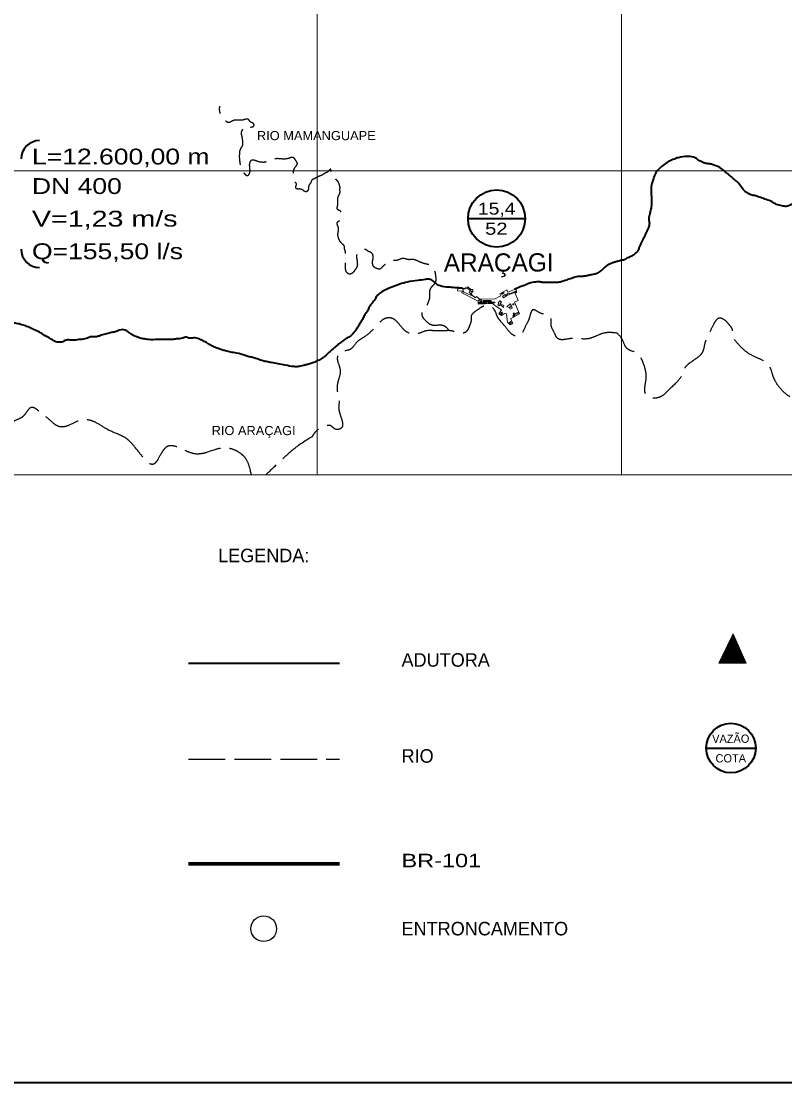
# Model space of a CAD drawing. Extents: x -4 to 42046, y -3 to 29697.
# Drawn here: x 27137 to 31133, y 10020 to 15575 of the extents above; entities that cross this region are included whole.
import ezdxf
from ezdxf.enums import TextEntityAlignment as Align

# ---------------------------------------------------------------- set-up
doc = ezdxf.new("R2010")
doc.units = 0
doc.header["$LTSCALE"] = 32
doc.linetypes.add('DOT_DASHED', pattern=[7.7, 5, -1.2, 0.3, -1.2])
doc.linetypes.add('LONG_DASHED', pattern=[7.5, 6, -1.5])
for name, color, linetype, lineweight in [('1', 7, 'DOT_DASHED', 13), ('4', 7, 'Continuous', 13), ('5', 7, 'LONG_DASHED', 25), ('6', 7, 'Continuous', 40), ('63', 7, 'Continuous', 25), ('8', 7, 'Continuous', 35), ('9', 7, 'Continuous', 40)]:
    doc.layers.add(name, color=color, linetype=linetype, lineweight=lineweight)

msp = doc.modelspace()

# ---------------------------------------------------------------- linework, layer by layer
at = {"layer": '1', "linetype": 'Continuous'}
for points in [[(29744.7, 14044.01), (29718.97, 14105.65), (29738.55, 14113.81), (29722.65, 14151.9), (29729.65, 14154.81), (29727.44, 14174.14), (29683.62, 14157.13), (29679.13, 14168.68), (29642.18, 14148.33), (29647.48, 14138.73), (29613.62, 14120.08), (29534.25, 14121.97), (29520.23, 14134.95), (29512.82, 14126.96), (29489.31, 14148.71), (29500.27, 14160.52), (29500.36, 14171.05), (29489.82, 14171.14), (29474.28, 14185.44), (29450.2, 14174.76), (29421.75, 14177.09), (29420.68, 14164.08), (29444.2, 14162.16), (29443.51, 14153.65), (29528.5, 14110.87), (29529.03, 14094.96), (29602.73, 14097.4), (29621.15, 14084.62), (29650.49, 14064.27), (29636.62, 14044.31), (29650.86, 14034.44), (29667.07, 14046.19), (29676.24, 14043.8), (29681.19, 13999.94), (29696.18, 13986.49), (29710.62, 13994.24), (29698.28, 14017.17)], [(29449.12, 14162.14), (29449.09, 14171.03), (29472.52, 14178.25), (29484.15, 14167.18), (29496.75, 14161.3), (29495.66, 14158.96), (29484.45, 14164.2), (29480.87, 14156.55), (29498.55, 14137.36), (29454.32, 14156.73)], [(29547.5, 14109.37), (29538.37, 14109.34), (29530.96, 14113.27), (29533.04, 14117.19), (29545.26, 14116.77)], [(29595.86, 14113.71), (29555.39, 14113.59), (29555.4, 14108.9), (29595.88, 14109.02)], [(29644.11, 14093.53), (29638.87, 14086.59), (29631.92, 14091.82), (29637.16, 14098.76), (29633.39, 14101.6), (29641.69, 14112.61), (29650.36, 14106.09), (29643.83, 14097.44), (29663, 14087.14), (29661.12, 14076.86)], [(29652.77, 14144.36), (29664.37, 14151.37), (29661.93, 14155.41), (29650.32, 14148.4)], [(29724.47, 14156.86), (29681.67, 14141.12), (29661.13, 14127.12), (29655.67, 14135.1), (29669.35, 14144.42), (29672.65, 14139.61), (29681.44, 14145.6), (29679.15, 14148.96), (29688.95, 14151.44), (29694.93, 14149.13), (29723.12, 14162.17)], [(29533.71, 14099.46), (29574.19, 14099.58), (29574.17, 14105.5), (29533.69, 14105.38)], [(29580.85, 14100.83), (29616.14, 14100.94), (29616.13, 14105.38), (29580.83, 14105.27)], [(29696.43, 14095.84), (29678.07, 14080.97), (29691.94, 14077.67), (29702.43, 14086.54)], [(29706.05, 14073.89), (29696.51, 14068.6), (29692.84, 14075.2), (29705.31, 14082.11)], [(29709.34, 14090.62), (29709.33, 14095.96), (29714.67, 14095.98), (29714.69, 14090.64)], [(29647.14, 14038.83), (29656.43, 14048.18), (29651.87, 14052.7), (29642.58, 14043.35)], [(29695.54, 13993.58), (29691.7, 13997.87), (29697.87, 14003.38), (29701.71, 13999.09)], [(29720.49, 14036.42), (29713.11, 14030.19), (29710.38, 14033.41), (29717.77, 14039.64)], [(29714.75, 14041.18), (29712.34, 14045.95), (29717.12, 14048.35), (29719.52, 14043.58)], [(29739.57, 14047.71), (29725.02, 14040.73), (29723.07, 14044.79), (29737.63, 14051.76)]]:
    msp.add_lwpolyline(points, close=True, dxfattribs=at)
at = {"layer": '4'}
for p, q in [((30814.89, 12269.39), (30878.99, 12333.49)), ((30817.49, 12274.82), (30878.12, 12335.45)), ((30820.09, 12280.25), (30877.25, 12337.41)), ((30822.69, 12285.68), (30876.38, 12339.36)), ((30825.29, 12291.11), (30875.51, 12341.32)), ((30827.89, 12296.54), (30874.64, 12343.28)), ((30830.5, 12301.97), (30873.77, 12345.24)), ((30833.1, 12307.4), (30872.9, 12347.2)), ((30835.7, 12312.83), (30872.03, 12349.16)), ((30838.3, 12318.25), (30871.17, 12351.12)), ((30840.9, 12323.68), (30870.3, 12353.08)), ((30843.5, 12329.11), (30869.43, 12355.04)), ((30846.1, 12334.54), (30868.56, 12357)), ((30848.7, 12339.97), (30867.69, 12358.96)), ((30851.3, 12345.4), (30866.82, 12360.92)), ((30853.91, 12350.83), (30865.95, 12362.88)), ((30856.51, 12356.26), (30865.08, 12364.84)), ((30859.11, 12361.69), (30864.21, 12366.8)), ((30861.71, 12367.12), (30863.34, 12368.76)), ((30788.88, 12215.09), (30887.68, 12313.89)), ((30791.48, 12220.52), (30886.81, 12315.85)), ((30791.57, 12214.96), (30888.54, 12311.93)), ((30794.08, 12225.95), (30885.94, 12317.81)), ((30794.42, 12214.97), (30889.41, 12309.97)), ((30796.68, 12231.38), (30885.07, 12319.77)), ((30797.26, 12214.99), (30890.28, 12308.01)), ((30799.28, 12236.81), (30884.2, 12321.73)), ((30800.1, 12215), (30891.15, 12306.05)), ((30801.88, 12242.24), (30883.33, 12323.69)), ((30802.95, 12215.02), (30892.02, 12304.09)), ((30804.48, 12247.67), (30882.46, 12325.65)), ((30805.79, 12215.03), (30892.89, 12302.13)), ((30807.09, 12253.1), (30881.59, 12327.61)), ((30808.63, 12215.05), (30893.76, 12300.18)), ((30809.69, 12258.53), (30880.72, 12329.57)), ((30811.48, 12215.07), (30894.63, 12298.22)), ((30812.29, 12263.96), (30879.85, 12331.53)), ((30814.32, 12215.08), (30895.5, 12296.26)), ((30817.16, 12215.1), (30896.36, 12294.3)), ((30820.01, 12215.11), (30897.23, 12292.34)), ((30822.85, 12215.13), (30898.1, 12290.38)), ((30825.69, 12215.14), (30898.97, 12288.42)), ((30828.54, 12215.16), (30899.84, 12286.46)), ((30831.38, 12215.17), (30900.71, 12284.5)), ((30834.22, 12215.19), (30901.58, 12282.54)), ((30837.07, 12215.2), (30902.45, 12280.58)), ((30839.91, 12215.22), (30903.32, 12278.62)), ((30842.76, 12215.23), (30904.19, 12276.66)), ((30845.6, 12215.25), (30905.05, 12274.7)), ((30848.44, 12215.26), (30905.92, 12272.74)), ((30851.29, 12215.28), (30906.79, 12270.78)), ((30854.13, 12215.29), (30907.66, 12268.82)), ((30856.97, 12215.31), (30908.53, 12266.86)), ((30859.82, 12215.32), (30909.4, 12264.9)), ((30862.66, 12215.34), (30910.27, 12262.94)), ((30865.5, 12215.35), (30911.14, 12260.99)), ((30868.35, 12215.37), (30912.01, 12259.03)), ((30871.19, 12215.38), (30912.87, 12257.07)), ((30874.03, 12215.4), (30913.74, 12255.11)), ((30876.88, 12215.41), (30914.61, 12253.15)), ((30879.72, 12215.43), (30915.48, 12251.19)), ((30882.56, 12215.44), (30916.35, 12249.23)), ((30885.41, 12215.46), (30917.22, 12247.27)), ((30888.25, 12215.47), (30918.09, 12245.31)), ((30891.1, 12215.49), (30918.96, 12243.35)), ((30893.94, 12215.5), (30919.83, 12241.39)), ((30896.78, 12215.52), (30920.7, 12239.43)), ((30899.63, 12215.53), (30921.56, 12237.47)), ((30902.47, 12215.55), (30922.43, 12235.51)), ((30905.31, 12215.56), (30923.3, 12233.55)), ((30908.16, 12215.58), (30924.17, 12231.59)), ((30911, 12215.59), (30925.04, 12229.63)), ((30913.84, 12215.61), (30925.91, 12227.67)), ((30916.69, 12215.62), (30926.78, 12225.72)), ((30919.53, 12215.64), (30927.65, 12223.76)), ((30922.37, 12215.65), (30928.52, 12221.8)), ((30925.22, 12215.67), (30929.38, 12219.84)), ((30928.06, 12215.68), (30930.25, 12217.88)), ((30930.9, 12215.7), (30931.12, 12215.92))]:
    msp.add_line(p, q, dxfattribs=at)
at = {"layer": '4', "lineweight": 70}
msp.add_line((28013.04, 11165.93), (28802.34, 11165.93), dxfattribs=at)
at = {"layer": '4'}
msp.add_lwpolyline([(30788.81, 12214.94), (30862.93, 12369.68), (30931.22, 12215.7)], close=True, dxfattribs=at)
at = {"layer": '4', "lineweight": 25}
msp.add_ellipse((28405.86, 10825.9), major_axis=(67.17, 0), ratio=0.998913, dxfattribs=at)
at = {"layer": '5'}
msp.add_line((28013.04, 11713.23), (28802.34, 11713.23), dxfattribs=at)
for points in [[(28681.07, 14756.16), (28666.12, 14748.56), (28658.14, 14744.4), (28654.18, 14734.4), (28645.37, 14720.96), (28641.95, 14713.99), (28640.13, 14699.54), (28636.45, 14688.89), (28627.7, 14682.68), (28618.09, 14685.74), (28607.33, 14693.45), (28593.7, 14697.23), (28582.8, 14697.2), (28575.17, 14700.52), (28574.24, 14709.88), (28577.53, 14723.84), (28570.3, 14733.9), (28563.78, 14745.31), (28561.74, 14765.64), (28561.72, 14774.64), (28563.58, 14795.4), (28570.56, 14810.9), (28579.59, 14822.74), (28582.01, 14831.3), (28575.97, 14842.69), (28567.58, 14856.11), (28559, 14862.1), (28540.88, 14859.19), (28524.81, 14854.86), (28495.79, 14854.78), (28464.7, 14854.69), (28448.29, 14848.89), (28425.87, 14842.11), (28413.87, 14837.48), (28394.09, 14837.42), (28381.18, 14839.15), (28354.5, 14848.03), (28340.09, 14846.12), (28333.5, 14837.46), (28331.73, 14807.61), (28331.8, 14783.03), (28326.41, 14771.66), (28320.49, 14765.87), (28309.11, 14773.47), (28296.19, 14786.49), (28289.36, 14803.08), (28284.38, 14824.43), (28280.39, 14852.73), (28280.31, 14881.38), (28282.29, 14898.51), (28288.86, 14913.45), (28297.12, 14930.43), (28297.08, 14941.31), (28293.13, 14967.62), (28290.12, 14995.38), (28296.41, 15010.02), (28304.17, 15021.73), (28320.74, 15021.78), (28343.4, 15021.85), (28353.86, 15026.51), (28353.83, 15037.39), (28338.94, 15046.69), (28324.03, 15062.23), (28297, 15058.26), (28262.9, 15058.15), (28242.93, 15053.71), (28221.03, 15045.12), (28206.15, 15053.36), (28194.4, 15071.47), (28182.22, 15088.42), (28176.42, 15101.74), (28176.33, 15130.85)], [(29377.54, 13955.04), (29362.5, 13972.34), (29338.58, 13983.93), (29289.16, 13983.78), (29261.34, 14000.36), (29246.86, 14014.76), (29236.81, 14033.05), (29236.75, 14055.82), (29243.36, 14073.06), (29258.32, 14084.76), (29267.15, 14103.67), (29275.95, 14132.02), (29275.85, 14164.78), (29286.34, 14186.47), (29300.73, 14201.51), (29307.35, 14214.85), (29307.28, 14240.4), (29300.52, 14270.92), (29282.12, 14296.41), (29252.11, 14305.21), (29211.52, 14320.64), (29190.96, 14327.79), (29162.08, 14327.71), (29137.63, 14333.74), (29098.79, 14323.08), (29078.24, 14323.02), (29045.22, 14304.26), (29026.59, 14289.39), (29016.32, 14279.05), (28995.38, 14282.21), (28983.76, 14288.94), (28975.33, 14310.81), (28978.78, 14339.8), (28972.28, 14361.03), (28951.32, 14372.24), (28940.35, 14379.62), (28917.82, 14375.68), (28905.93, 14366.31), (28892.78, 14352.8), (28892.84, 14332.6), (28895.39, 14313.31), (28895.44, 14296.28), (28890.26, 14283.33), (28881.22, 14270.36), (28873.98, 14259.9), (28865.6, 14254.2), (28854.03, 14251.89), (28844.94, 14256.63), (28836.73, 14267.51), (28834.41, 14286.34), (28834.33, 14310.4), (28834.27, 14331.06), (28834.18, 14361.25), (28831.87, 14375.32), (28829.12, 14383.71), (28829.09, 14394.59), (28817.24, 14409.55), (28805.17, 14423.82), (28798.08, 14440.37), (28794.64, 14453.53), (28797.06, 14478.28), (28797.01, 14496.13), (28791.52, 14510.68), (28793.39, 14525.09), (28808.56, 14535.7), (28808.48, 14563.06), (28808.43, 14580.83), (28794.17, 14588.15), (28794.08, 14617.27), (28793.99, 14648.55), (28799.38, 14664.19), (28805.06, 14677.5), (28805.02, 14692.2), (28804.97, 14709.52), (28802.15, 14719.41), (28798.25, 14730.99), (28792.35, 14739.02), (28784.29, 14747.35), (28779.95, 14750.27), (28775.22, 14759.78), (28770.5, 14770.11), (28767.13, 14779.09), (28760.1, 14787.26), (28758.17, 14795.45), (28756.88, 14801.02), (28748.23, 14795.02), (28741.8, 14787.69), (28725.37, 14778.83), (28710.42, 14769.52), (28694.32, 14763.05), (28681.07, 14756.16)], [(36427.45, 14204.37), (36372.08, 14108.75), (36305.48, 13999.35), (36136.53, 13956.58), (35847.84, 13902.88), (35759.27, 14075.23), (35713.31, 14131.45), (35636.31, 13965.66), (35506.34, 13841.99), (35249.2, 13841.22), (35248.87, 13953.94), (35237.98, 13953.91), (35181.75, 14017.15), (35181.99, 13936.13), (35083.37, 13935.84), (34941.94, 14111.55), (34878.67, 14069.09), (34924.95, 13903.67), (34925.39, 13755.72), (34784.49, 13755.3), (34615.25, 13811.16), (34245.39, 13810.06), (34122.35, 13832.82), (34069.68, 13894.69), (33994.34, 13957.69), (33936.87, 14030.29), (33885.43, 14077.85), (33815, 14095.54), (33725.5, 14107.2), (33699.12, 14152.45), (33675.07, 14216.8), (33661.79, 14268.06), (33661.7, 14300.26), (33613.98, 14300.12), (33567.46, 14299.98), (33502.97, 14324.84), (33452.79, 14349.75), (33398.87, 14331.57), (33350.01, 14293.67), (33293.57, 14227.42), (33250.69, 14165.35), (33219.6, 14103.89), (33186.12, 14054.83), (33144.35, 14012.22), (33017.72, 14018.47), (32898.55, 14018.11), (32797.64, 14011.13), (32759.36, 14002.5), (32679.24, 13997.75), (32638.82, 14023.47), (32613.66, 14098.65), (32563.66, 14147.91), (32516.03, 14157.74), (32436.26, 14122.82), (32339.57, 14047.25), (32213.58, 14017.71), (32118.67, 13976.03), (32019.97, 13942.8), (31933.49, 13914.31), (31870.59, 13865.2), (31815.23, 13814.22), (31727.15, 13748.91), (31542.32, 13629.09), (31345.37, 13573.61), (31183.12, 13596.83), (31071.72, 13720.02), (31052.85, 13771.11), (30960.36, 13826.98), (30917.86, 13856.79), (30872.81, 13905.59), (30859.91, 13927.17), (30859.82, 13959.59), (30844.2, 13985.21), (30819.14, 14010.8), (30788.71, 14020.84), (30765.82, 13998.48), (30739.64, 13945.05), (30715.48, 13891.62), (30703.46, 13845.65), (30656.32, 13800.26), (30609.83, 13759.59), (30594.41, 13722.4), (30534.81, 13654.39), (30461.71, 13603.36), (30408.49, 13619.75), (30408.23, 13708.36), (30393.83, 13782.75), (30361.77, 13835.83), (30307.34, 13862.84), (30283.58, 13907.67), (30256.3, 13943.03)], [(30256.3, 13943.03), (30186.59, 13942.82), (30108.7, 13914.24), (30010.63, 13913.95), (29946.83, 13913.76), (29925.46, 13947.96), (29909.98, 13988.08), (29909.89, 14021.16), (29848.36, 14050.52), (29815.76, 14065.5), (29796.11, 14022.42), (29772.43, 13971.18), (29752.18, 13936.23), (29732.44, 13926.87), (29696.33, 13945.37), (29665.99, 13982.49), (29630.38, 14027.16), (29608.15, 14071.86), (29569.73, 14086.29), (29522.71, 14062.89), (29491.41, 14029.65), (29491.47, 14008.14), (29482.83, 13981.36), (29474.17, 13960.41), (29455.03, 13944.07), (29386.1, 13955.07), (29352.67, 13954.97), (29304, 13954.82), (29255.91, 13954.68), (29216.07, 13941.07), (29172.68, 13940.95), (29141.54, 13959.03), (29108.59, 13997.64), (29080.96, 14019.26), (29041.08, 14019.14), (29005.98, 13992.06), (28960.89, 13945.26), (28924.02, 13917.67), (28891.87, 13894.36), (28861.18, 13859.21), (28816.69, 13845.34), (28792.6, 13821.11), (28799.36, 13776.12), (28806.57, 13743.45), (28799.57, 13706), (28791.14, 13672.81), (28791.25, 13638.7), (28797.96, 13612.67), (28798.14, 13550.6)], [(27654.38, 13409.42), (27579.6, 13443.73), (27529.72, 13474.09), (27454.19, 13489.13), (27394.85, 13464.06), (27340.28, 13452.65), (27285.56, 13488.62), (27231.63, 13532.63), (27190.61, 13554.19), (27152.2, 13513.13), (27106.91, 13486.18), (27065.69, 13475.06), (27029.89, 13492.14), (26998.84, 13531.24), (26943.02, 13575.07), (26907.27, 13574.97), (26894.31, 13541.24), (26878.63, 13495.82), (26864.29, 13464.84), (26876.8, 13418.81), (26893.41, 13382.42), (26893.48, 13356.3), (26878.41, 13339.06), (26867.52, 13339.03), (26842.62, 13351.33), (26801.37, 13351.21), (26767.05, 13334.61), (26721.05, 13314.53), (26704.57, 13304.86)], [(28798.14, 13550.6), (28803.79, 13523.54), (28817.93, 13475.24), (28814.51, 13448.52), (28778.59, 13441.42), (28757.88, 13457.57), (28731.48, 13457.49), (28695.91, 13442.44), (28671.81, 13420.11), (28658.83, 13400.35)], [(28340.85, 13201.8), (28311.65, 13286.52), (28197.81, 13341.95), (28043.48, 13311.46), (27897.54, 13347.49), (27833.46, 13259.36), (27689.37, 13389.77), (27649, 13411.88)], [(28658.83, 13400.35), (28558.16, 13332.29), (28496.12, 13276.34), (28417.71, 13201.8)]]:
    msp.add_spline(points, degree=3, dxfattribs=at)
at = {"layer": '6'}
for p, q in [((29446.4, 14177.64), (29450.2, 14174.76)), ((28013.04, 12215.7), (28802.34, 12215.7))]:
    msp.add_line(p, q, dxfattribs=at)
for points in [[(30944.65, 14672.29), (30931.29, 14680.28), (30911.33, 14700.35), (30891.86, 14727.76), (30870.05, 14746.34), (30849.04, 14765.08), (30832.88, 14777.2), (30812.3, 14795.26), (30787.37, 14812.54), (30777.44, 14816.81), (30757.86, 14823.96), (30740.66, 14828.34), (30719.87, 14831.39), (30699.32, 14839.14), (30682.65, 14847.19), (30667.96, 14858.66), (30654.91, 14863.47), (30620.82, 14867.95), (30577.51, 14861.04), (30556.02, 14854.18), (30525.64, 14840.24), (30500.47, 14824.26), (30477.22, 14805.1), (30458.56, 14781.33), (30445.81, 14752.22), (30434.39, 14708.94), (30434.71, 14602.03), (30429.63, 14580.01), (30425.17, 14562.16), (30422.04, 14548.98), (30422.09, 14531.86), (30424.38, 14521.99), (30424.41, 14513.09), (30422.78, 14505.82), (30420.46, 14494.97), (30417.54, 14487.24), (30411.92, 14476.57), (30402.06, 14457.68), (30394.96, 14441.93), (30388.82, 14429.56), (30381.37, 14415.03), (30374.74, 14399.94), (30369.07, 14386.02), (30366.03, 14376.99), (30362.27, 14371.95), (30358.88, 14366.45), (30355.53, 14363.37), (30349.88, 14359.03), (30345.41, 14353.95), (30335.9, 14348.87), (30328.2, 14343.78), (30320.01, 14340.16), (30317.53, 14338.21), (30316.91, 14338.21), (30297.19, 14327.93), (30281.02, 14324.07), (30265.95, 14320.26), (30249.83, 14316.11), (30234.81, 14311.53), (30220.33, 14306.05), (30205.65, 14297.87), (30194.44, 14289.33), (30183.16, 14279.64), (30174.66, 14272.35), (30165.06, 14265.42), (30154.75, 14258.41), (30144.5, 14253.25), (30135.72, 14250.87), (30112.64, 14245.98), (30092.21, 14241.83), (30072.26, 14239.39), (30050, 14239.32), (30035.77, 14235.29), (30022.7, 14231.21), (30010.68, 14227.56), (29996.9, 14222.77), (29983.6, 14218.45), (29963.71, 14211.14), (29940.96, 14207.67), (29912.37, 14207.59), (29886.98, 14207.51), (29874.23, 14207.47), (29867.24, 14207.45), (29851.27, 14210.95), (29835.86, 14210.91), (29804.55, 14205.65), (29781.84, 14198.22), (29768.53, 14192.91), (29748.61, 14184.63), (29718.22, 14170.66)], [(31993.33, 14641.51), (31977.39, 14632.76), (31966.05, 14626.91), (31955.84, 14622.53), (31942.33, 14622.49), (31921.24, 14626.06), (31901.35, 14633.07), (31890.74, 14638.72), (31872.85, 14649.48), (31847.21, 14659.4), (31814.59, 14659.31), (31794.5, 14648.26), (31772.26, 14648.2), (31747.34, 14644.99), (31722.43, 14648.12), (31694.49, 14656.09), (31679.25, 14656.04), (31648.99, 14655.95), (31614.34, 14655.85), (31587.85, 14660.7), (31562.21, 14665.62), (31552.52, 14670.13), (31538.43, 14676.65), (31512.71, 14676.57), (31472.36, 14668.31), (31435.19, 14662.53), (31402.23, 14658.01), (31353.61, 14661.77), (31315.81, 14658.19), (31260.06, 14639.31), (31235.86, 14633.79), (31198.93, 14626.82), (31157.69, 14610.89), (31141.51, 14606.16), (31118.48, 14609.26), (31089.76, 14616.89), (31067.66, 14630.19), (31036, 14641.6), (31007.61, 14652.24), (30980.91, 14661.05), (30956.29, 14667.04), (30941.87, 14672.76)], [(29446.4, 14177.64), (29370.69, 14183.49), (29330.14, 14189.6), (29318.9, 14194.38), (29298.43, 14210.55), (29278.11, 14224.01), (29252.33, 14223.94), (29212.01, 14218.05), (29158.06, 14209.94), (29117.65, 14199.27), (29063.04, 14177.81), (29023.48, 14158.18), (29003.7, 14143.08), (28990.45, 14124.71), (28983.09, 14112.11), (28975.07, 14101.35), (28962.41, 14086.18), (28951.9, 14065.53), (28941.45, 14048.4), (28930.87, 14029.63), (28919.58, 14009.37), (28908, 13989.93), (28897.63, 13973.91), (28884.11, 13953.94), (28871.44, 13937.89), (28862.68, 13929.52), (28852.03, 13922.38), (28832.51, 13911.27), (28813.8, 13897.52), (28794.93, 13882.22), (28781.63, 13871.69), (28764.83, 13857.07), (28749.39, 13843.23), (28734.51, 13829.62), (28717.17, 13815.82), (28695.36, 13802.06), (28674.08, 13791.58), (28651.98, 13783.65), (28630.15, 13777.31), (28611.66, 13772.94), (28585.9, 13767.52), (28564.65, 13767.45), (28518.6, 13775.19), (28481.89, 13782.03), (28445.68, 13788.47), (28420.46, 13793.74), (28395.54, 13799.16), (28371.15, 13808.46), (28347.94, 13815.84), (28327.97, 13819.7), (28309.02, 13825.21)], [(28309.3, 13825.11), (28263.62, 13838.16), (28232.58, 13843.71), (28206.55, 13849.91), (28186.34, 13855.68), (28167.46, 13861.77), (28148.04, 13870.08), (28128.55, 13879.11), (28105.98, 13893.76), (28082.4, 13905.46), (28060.53, 13915.22), (28033.62, 13917.1), (28014.45, 13917.04), (28001.8, 13921.91), (27980.26, 13916.81), (27948.97, 13912.36), (27929.78, 13909.59), (27904.37, 13909.52), (27851.94, 13909.36), (27803.87, 13909.22), (27790.62, 13911.34), (27768.51, 13914.09), (27750.86, 13919.97), (27732.13, 13927.16), (27721.26, 13932.65), (27708.63, 13940.14), (27698.25, 13948.74), (27680.22, 13959.24), (27652.86, 13959.16), (27638.81, 13952.7), (27617.13, 13947.87), (27596.69, 13943.13), (27582.4, 13938.85), (27569.21, 13936.34), (27555.09, 13932.13), (27543.82, 13927.83), (27535.11, 13924.84), (27525.27, 13923.07), (27499.6, 13922.99), (27483.26, 13917.23), (27470.01, 13912.69), (27454.58, 13909.21), (27437.29, 13909.16), (27421.23, 13906.56), (27406.35, 13906.52), (27395.39, 13906.49), (27375.23, 13906.43), (27359.53, 13899.96), (27348.07, 13895.38), (27332.81, 13895.33), (27317.81, 13897.22), (27304.9, 13904.06), (27283.45, 13917.4), (27255.46, 13933.38), (27232.22, 13947.14), (27201.77, 13962.28), (27172.84, 13975.29), (27147.53, 13984.69), (27119.72, 13992.15), (27091.92, 13996.89), (27071.02, 14003.05), (27050.28, 14007.6), (27026.02, 14013.12), (27006.12, 14017.56), (26983.69, 14022.43), (26957.07, 14027.19), (26947.02, 14027.16), (26939.84, 14029.72), (26925.7, 14035.51), (26902.98, 14038.77), (26876.52, 14041.93), (26851.83, 14045.57), (26835.56, 14048.36), (26818.05, 14052.5), (26800.32, 14059.17), (26778.54, 14059.1), (26740.55, 14061.01), (26693.56, 14060.87), (26674.82, 14060.81), (26573.28, 14060.51), (26522.89, 14057.05), (26449.44, 14056.84), (26358.85, 14056.57), (26311.17, 14060.6), (26266.64, 14064.1)]]:
    msp.add_spline(points, degree=3, dxfattribs=at)
at = {"layer": '63', "lineweight": 13}
for p, q in [((28686.24, 13201.8), (28686.24, 18929.66)), ((30279.04, 13201.8), (30279.04, 18929.66)), ((41110.1, 14792.87), (23907.83, 14792.87)), ((41110.1, 13201.8), (23907.83, 13201.8))]:
    msp.add_line(p, q, dxfattribs=at)
at = {"layer": '63', "lineweight": 35}
msp.add_lwpolyline([(41110.1, 10019.66), (23907.83, 10019.66), (23907.83, 18929.66)], dxfattribs=at)
at = {"layer": '8'}
for centre, start_param, end_param in [((27232.25, 14854.98), 4.712389, 6.2831853), ((27232.25, 14854.98), 4.712389, 6.2831853), ((27232.25, 14854.98), 4.712389, 6.2831853), ((27232.25, 14381.6), 6.2831853, 7.8539816)]:
    msp.add_ellipse(centre, major_axis=(-95.57, 0), ratio=0.998913, start_param=start_param, end_param=end_param, dxfattribs=at)
at = {"layer": '9', "lineweight": 35}
for p, q in [((29475.67, 14542.55), (29774.93, 14542.55)), ((30722.06, 11771.23), (30981.16, 11771.23))]:
    msp.add_line(p, q, dxfattribs=at)
for centre, radius in [((29625.3, 14542.55), 149.63), ((30851.61, 11771.23), 129.55)]:
    msp.add_circle(centre, radius, dxfattribs=at)

# ---------------------------------------------------------------- texts
at = {"layer": '5', "width": 1.05}
for s, rotation, p in [('RIO MAMANGUAPE', 0.006, (28370.48, 14952.86)), ('RIO ARAÇAGI', 359.911, (28133.5, 13409.6))]:
    msp.add_text(s, height=47.73, rotation=rotation, dxfattribs=at).set_placement(p)
at = {"layer": '63'}
for s, p in [('LEGENDA:', (28167.07, 12743.99)), ('ADUTORA', (29127.37, 12197.21)), ('RIO', (29127.37, 11694.74)), ('ENTRONCAMENTO', (29127.37, 10791.09))]:
    msp.add_text(s, height=70.71, dxfattribs=at).set_placement(p)
at = {"layer": '63', "width": 1.3}
msp.add_text('BR-101', height=70.71, dxfattribs=at).set_placement((29127.37, 11147.44))
at = {"layer": '8'}
for s, width, p in [('L=12.600,00 m', 1.25, (27192.98, 14825.45)), ('DN 400', 1.25, (27192.98, 14670.96)), ('V=1,23 m/s', 1.35, (27192.98, 14500.37)), ('Q=155,50 l/s', 1.25, (27192.98, 14329.78))]:
    msp.add_text(s, height=82.98, dxfattribs=dict(at, width=width)).set_placement(p)
at = {"layer": '9'}
for s, width, p in [('15,4', 1.2, (29625.55, 14563.05)), ('52', 1.25, (29623.7, 14457.97))]:
    msp.add_text(s, height=63, rotation=0.17, dxfattribs=dict(at, width=width)).set_placement(p, align=Align.CENTER)
msp.add_text('ARAÇAGI', height=95.46, rotation=0.17, dxfattribs=at).set_placement((29348.57, 14263.96))
for s, p in [('VAZÃO', (30850.83, 11798.72)), ('COTA', (30850.83, 11696.2))]:
    msp.add_text(s, height=43, rotation=0.17, dxfattribs=at).set_placement(p, align=Align.CENTER)

doc.saveas('drawing.dxf')
